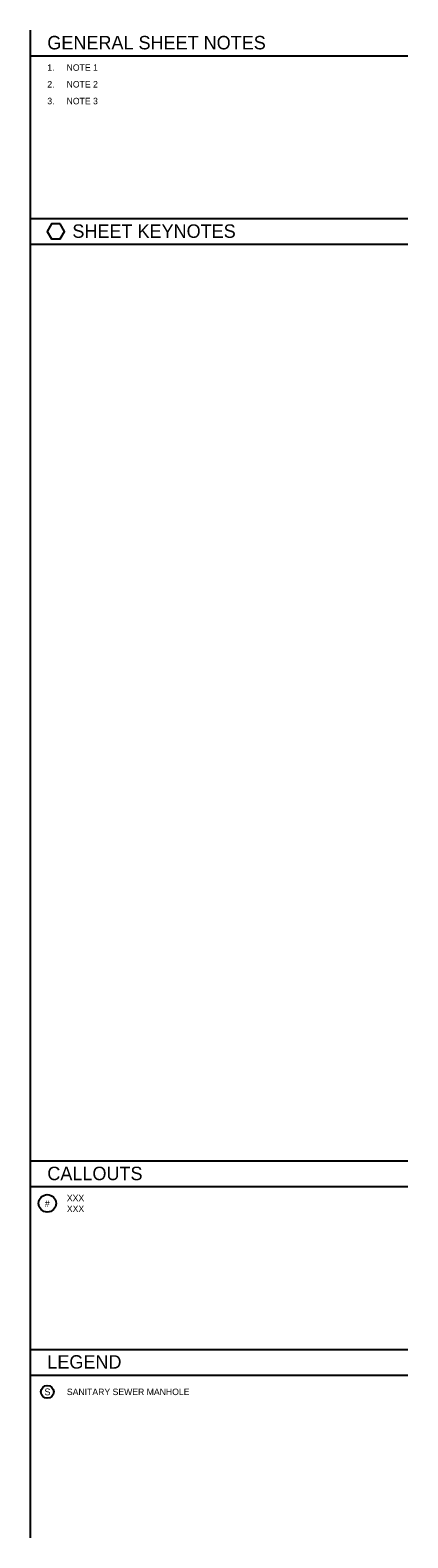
# Model space of a CAD drawing. Extents: x 0.63 to 0.77, y 0.012 to 0.572.
import ezdxf

# ---------------------------------------------------------------- set-up
doc = ezdxf.new("R2010")
doc.units = 0
for name, color, linetype in [('G-ANNO-KEYN', 7, 'Continuous'), ('G-ANNO-SYMB', 7, 'Continuous'), ('G-ANNO-TEXT', 7, 'Continuous'), ('G-DETL-GRPH', 7, 'Continuous')]:
    doc.layers.add(name, color=color, linetype=linetype)

msp = doc.modelspace()

# ---------------------------------------------------------------- linework, layer by layer
at = {"layer": 'G-ANNO-KEYN'}
msp.add_lwpolyline([(0.64124, 0.50048), (0.63803, 0.50048), (0.63642, 0.49771), (0.63803, 0.49493), (0.64124, 0.49493), (0.64284, 0.49771)], close=True, dxfattribs=at)
at = {"layer": 'G-ANNO-SYMB'}
for centre, radius in [((0.63642, 0.13669), 0.00325), ((0.63642, 0.06669), 0.00238)]:
    msp.add_circle(centre, radius, dxfattribs=at)
at = {"layer": 'G-DETL-GRPH'}
for p, q in [((0.63007, 0.57247), (0.63007, 0.01247)), ((0.63007, 0.56294), (0.77007, 0.56294)), ((0.63007, 0.50247), (0.77007, 0.50247)), ((0.63007, 0.49294), (0.77007, 0.49294)), ((0.63007, 0.15247), (0.77007, 0.15247)), ((0.63007, 0.14294), (0.77007, 0.14294)), ((0.63007, 0.08247), (0.77007, 0.08247)), ((0.63007, 0.07294), (0.77007, 0.07294))]:
    msp.add_line(p, q, dxfattribs=at)

# ---------------------------------------------------------------- texts
at = {"layer": 'G-ANNO-KEYN'}
msp.add_text('     SHEET KEYNOTES', height=0.005, dxfattribs=at).set_placement((0.63642, 0.49533))
at = {"layer": 'G-ANNO-SYMB'}
for s, height, p in [('#', 0.0024, (0.63551, 0.13549)), ('S', 0.0025, (0.63535, 0.06544))]:
    msp.add_text(s, height=height, dxfattribs=at).set_placement(p)
at = {"layer": 'G-ANNO-TEXT'}
for s, height, p in [('GENERAL SHEET NOTES', 0.005, (0.63642, 0.56533)), ('1.', 0.0024, (0.63642, 0.55737)), ('NOTE 1', 0.0024, (0.64357, 0.55737)), ('2.', 0.0024, (0.63642, 0.55116)), ('NOTE 2', 0.0024, (0.64357, 0.55116)), ('3.', 0.0024, (0.63642, 0.54494)), ('NOTE 3', 0.0024, (0.64357, 0.54494)), ('CALLOUTS', 0.005, (0.63642, 0.14532)), ('XXX', 0.0024, (0.64367, 0.13749)), ('XXX', 0.0024, (0.64367, 0.13349)), ('LEGEND', 0.005, (0.63642, 0.07532)), ('SANITARY SEWER MANHOLE', 0.0024, (0.64367, 0.06549))]:
    msp.add_text(s, height=height, dxfattribs=at).set_placement(p)

doc.saveas('drawing.dxf')
